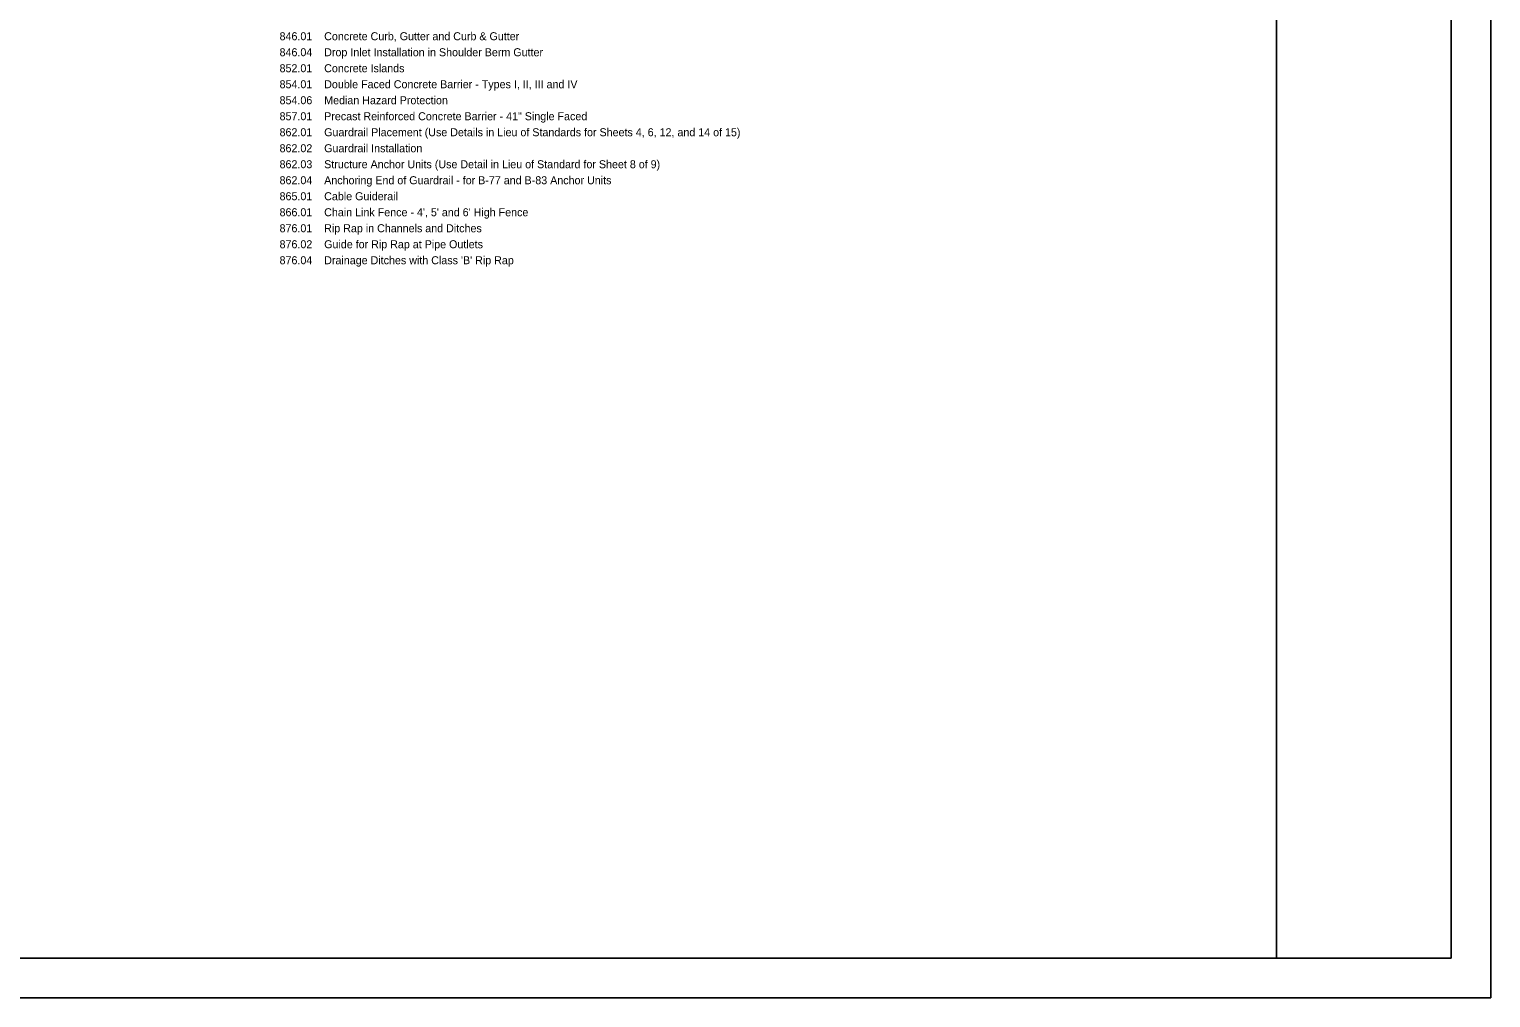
# Model space of a CAD drawing. Extents: x 1844369 to 1844800, y 671424 to 671721.
# Drawn here: x 1844512.4 to 1844581.8, y 671501.1 to 671547.1 of the extents above; entities that cross this region are included whole.
import ezdxf

# ---------------------------------------------------------------- set-up
doc = ezdxf.new("R2010")
doc.units = 0
for name, color, linetype in [('Sheet Data Text CELL', 7, 'Continuous'), ('Sheet_Clip_Boundary_CELL', 7, 'Continuous'), ('Sheet_Plan_CELL', 7, 'Continuous')]:
    doc.layers.add(name, color=color, linetype=linetype)

msp = doc.modelspace()

# ---------------------------------------------------------------- linework, layer by layer
at = {"layer": 'Sheet_Clip_Boundary_CELL'}
msp.add_lwpolyline([(1844581.788, 671593.106), (1844440.123, 671593.106), (1844440.123, 671501.068), (1844581.788, 671501.068)], close=True, dxfattribs=at)
at = {"layer": 'Sheet_Plan_CELL'}
for p, q in [((1844571.615, 671502.951), (1844571.617, 671591.223)), ((1844579.903, 671502.951), (1844579.905, 671591.223)), ((1844443.144, 671502.951), (1844579.903, 671502.951))]:
    msp.add_line(p, q, dxfattribs=at)

# ---------------------------------------------------------------- texts
at = {"layer": 'Sheet Data Text CELL'}
for s, p in [('846.01    Concrete Curb, Gutter and Curb & Gutter', (1844524.261, 671546.55)), ('846.04    Drop Inlet Installation in Shoulder Berm Gutter', (1844524.261, 671545.79)), ('852.01    Concrete Islands', (1844524.261, 671545.03)), ('854.01    Double Faced Concrete Barrier - Types I, II, III and IV', (1844524.261, 671544.27)), ('854.06    Median Hazard Protection', (1844524.261, 671543.51)), ('857.01    Precast Reinforced Concrete Barrier - 41" Single Faced', (1844524.261, 671542.75)), ('862.01    Guardrail Placement (Use Details in Lieu of Standards for Sheets 4, 6, 12, and 14 of 15)', (1844524.261, 671541.99)), ('862.02    Guardrail Installation', (1844524.261, 671541.23)), ('862.03    Structure Anchor Units (Use Detail in Lieu of Standard for Sheet 8 of 9)', (1844524.261, 671540.47)), ('862.04    Anchoring End of Guardrail - for B-77 and B-83 Anchor Units', (1844524.261, 671539.71)), ('865.01    Cable Guiderail', (1844524.261, 671538.95)), ("866.01    Chain Link Fence - 4', 5' and 6' High Fence", (1844524.261, 671538.19)), ('876.01    Rip Rap in Channels and Ditches', (1844524.261, 671537.43)), ('876.02    Guide for Rip Rap at Pipe Outlets', (1844524.261, 671536.67)), ("876.04    Drainage Ditches with Class 'B' Rip Rap", (1844524.261, 671535.91))]:
    msp.add_text(s, height=0.38, dxfattribs=at).set_placement(p)

doc.saveas('drawing.dxf')
